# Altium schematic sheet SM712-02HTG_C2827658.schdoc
size 127 x 101 mm
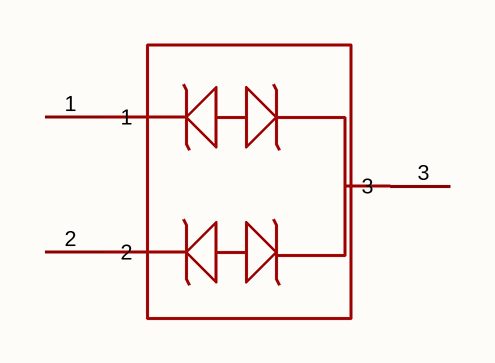
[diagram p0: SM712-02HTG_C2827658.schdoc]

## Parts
D?  sm712-02htg  [SOT-23_L2.9-W1.3-P1.90-LS2.4-BR]  (value not drawn)

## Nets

Not connected (* = marked no-connect by the designer): D? 1 2 3

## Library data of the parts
D? = sm712-02htg: 极性:双向;反向截止电压(Vrwm):7V;最大钳位电压:26V;峰值脉冲电流(Ipp):17A;峰值脉冲功率(Ppp):450W;击穿电压:13.3V;; Manufacturer: TECH PUBLIC(台舟); Symbol: SM712-02HTG_C2827658; AddInBom: yes; ModelId: c62791f0466c4ae2a892c056b845b0ca; ModelName: SOT-23-3P_L2.9-W1.3-H1.0-LS2.4-P0.95; ModelTransform: 98.64468,114.173,0,180,0,0,0.001,-0.002,0; polarity: 双向; Reverse Stand-Off Voltage (Vrwm): 7V; Maximum Clamping Voltage: 26V; Peak Pulse Current (Ipp): 17A; Peak Pulse Power Dissipation (Ppp): 450W; Breakdown Voltage: 13.3V; Reverse Leakage Current (Ir): 2uA; Number of Lines: 双路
